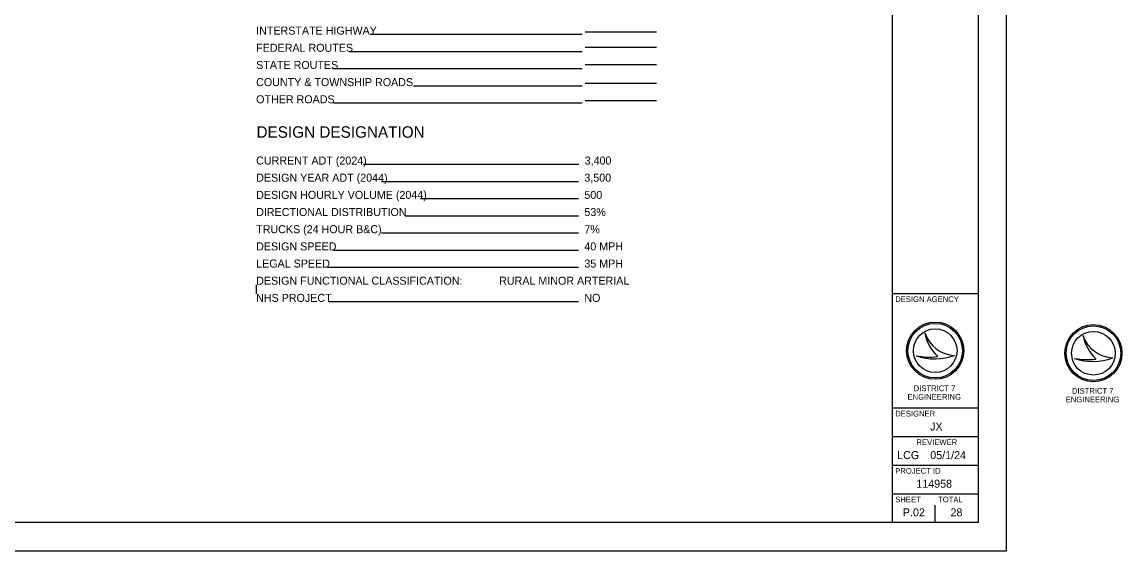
# Model space of a CAD drawing. Extents: x 831 to 1552, y 430 to 870.
# Drawn here: x 1166.7 to 1551.6, y 430 to 614.9 of the extents above; entities that cross this region are included whole.
import ezdxf

# ---------------------------------------------------------------- set-up
doc = ezdxf.new("R2010")
doc.units = 0
for name, color, linetype in [('SC_Scratch1', 7, 'Continuous'), ('SH_Border', 7, 'Continuous'), ('SH_Cut_Line', 7, 'Continuous'), ('SH_Data', 7, 'Continuous'), ('SH_Text', 7, 'Continuous')]:
    doc.layers.add(name, color=color, linetype=linetype)

msp = doc.modelspace()

# ---------------------------------------------------------------- linework, layer by layer
at = {"layer": 'SC_Scratch1'}
for p, q in [((1248.65, 523.06), (1248.65, 519.86)), ((1267.93, 440), (1064.6, 440)), ((1471.27, 440), (1267.93, 440))]:
    msp.add_line(p, q, dxfattribs=at)
at = {"layer": 'SH_Border'}
for p, q in [((1471.27, 440), (1471.27, 860)), ((1471.27, 520), (1501.27, 520)), ((1471.27, 480), (1501.27, 480)), ((1471.27, 470), (1501.27, 470)), ((1471.27, 460), (1501.27, 460)), ((1471.27, 450), (1501.27, 450))]:
    msp.add_line(p, q, dxfattribs=at)
msp.add_lwpolyline([(861.27, 860), (1501.27, 860), (1501.27, 440), (861.27, 440)], close=True, dxfattribs=at)
at = {"layer": 'SH_Cut_Line'}
msp.add_lwpolyline([(831.27, 430), (1511.27, 430), (1511.27, 870), (831.27, 870)], close=True, dxfattribs=at)
at = {"layer": 'SH_Data'}
for p, q in [((1362.77, 610.47), (1288.56, 610.47)), ((1388.77, 611.35), (1363.77, 611.35)), ((1362.77, 604.47), (1281.15, 604.47)), ((1388.77, 605.92), (1363.77, 605.92)), ((1362.77, 598.47), (1275.34, 598.47)), ((1388.77, 599.92), (1363.77, 599.92)), ((1388.77, 593.38), (1363.77, 593.38)), ((1362.77, 592.47), (1303.67, 592.47)), ((1362.77, 586.47), (1275.71, 586.47)), ((1388.77, 587.38), (1363.77, 587.38)), ((1361.61, 565.06), (1286.19, 565.06)), ((1361.5, 559.06), (1292.54, 559.06)), ((1361.5, 553.06), (1306.21, 553.06)), ((1361.5, 547.06), (1300.84, 547.06)), ((1361.5, 541.06), (1292.54, 541.06)), ((1361.5, 535.06), (1275.69, 535.06)), ((1361.5, 529.06), (1273.61, 529.06)), ((1361.5, 517.06), (1274.1, 517.06)), ((1482.62, 506.19), (1482.62, 506.19)), ((1537.98, 505.3), (1537.98, 505.3)), ((1479.61, 498.19), (1479.61, 498.19)), ((1486.27, 500), (1486.27, 500)), ((1493.01, 498.37), (1493.01, 498.37)), ((1534.98, 497.3), (1534.98, 497.3)), ((1548.38, 497.48), (1548.38, 497.48)), ((1478.77, 443.5), (1478.77, 443.5)), ((1486.27, 440), (1486.27, 446))]:
    msp.add_line(p, q, dxfattribs=at)
for centre, radius in [((1486.27, 500), 10), ((1486.27, 500), 9.54), ((1486.27, 500), 9.54), ((1541.63, 499.11), 10), ((1541.63, 499.11), 9.54), ((1541.63, 499.11), 9.54), ((1486.27, 500), 7.64), ((1541.63, 499.11), 7.64)]:
    msp.add_circle(centre, radius, dxfattribs=at)
for centre, radius, start, end in [((1493.59, 509.95), 11.6, 198.9257, 198.9319), ((1498.2, 509.4), 15.91, 191.6379, 191.6421), ((1493.59, 509.95), 11.6, 198.9319, 267.1657), ((1498.2, 509.4), 15.91, 191.6421, 226.0947), ((1548.95, 509.06), 11.6, 198.9257, 198.9319), ((1553.57, 508.51), 15.91, 191.6379, 191.6421), ((1548.95, 509.06), 11.6, 198.9319, 267.1657), ((1553.57, 508.51), 15.91, 191.6421, 226.0947), ((1486.05, 517.4), 20.26, 251.4576, 290.0832), ((1484.23, 523.09), 25.32, 259.4964, 259.4995), ((1486.05, 517.4), 20.26, 251.4527, 251.4576), ((1484.23, 523.09), 25.32, 259.4995, 276.6672), ((1541.42, 516.51), 20.26, 251.4576, 290.0832), ((1539.59, 522.19), 25.32, 259.4964, 259.4995), ((1541.42, 516.51), 20.26, 251.4527, 251.4576), ((1539.59, 522.19), 25.32, 259.4995, 276.6672)]:
    msp.add_arc(centre, radius, start, end, dxfattribs=at)

# ---------------------------------------------------------------- texts
for s, height, p in [('DESIGN DESIGNATION', 4, (1248.77, 574.43)), ('DESIGN AGENCY', 2, (1472.27, 517)), ('DESIGNER', 2, (1472.27, 477)), ('JX', 2.8, (1484.49, 472.1)), ('REVIEWER', 2, (1479.7, 467)), ('LCG', 2.8, (1472.97, 462.1)), ('05/1/24', 2.8, (1484.54, 462.1)), ('PROJECT ID', 2, (1472.27, 457)), ('114958', 2.8, (1479.65, 452.1)), ('SHEET', 2, (1472.27, 447)), ('TOTAL', 2, (1487.27, 447)), ('P.02', 2.8, (1474.96, 442.1)), ('28', 2.8, (1491.62, 442.1))]:
    msp.add_text(s, height=height, dxfattribs=at).set_placement(p)
at = {"layer": 'SH_Text'}
for s, height, p in [('INTERSTATE HIGHWAY', 2.8, (1248.65, 610.47)), ('FEDERAL ROUTES', 2.8, (1248.65, 604.47)), ('STATE ROUTES', 2.8, (1248.65, 598.47)), ('COUNTY & TOWNSHIP ROADS', 2.8, (1248.65, 592.47)), ('OTHER ROADS', 2.8, (1248.65, 586.47)), ('CURRENT ADT (2024)', 2.8, (1248.65, 565.06)), ('3,400', 2.8, (1363.61, 565.06)), ('DESIGN YEAR ADT (2044)', 2.8, (1248.65, 559.06)), ('3,500', 2.8, (1363.5, 559.06)), ('DESIGN HOURLY VOLUME (2044)', 2.8, (1248.65, 553.06)), ('500', 2.8, (1363.5, 553.06)), ('DIRECTIONAL DISTRIBUTION', 2.8, (1248.65, 547.06)), ('53%', 2.8, (1363.5, 547.06)), ('TRUCKS (24 HOUR B&C)', 2.8, (1248.65, 541.06)), ('7%', 2.8, (1363.5, 541.06)), ('DESIGN SPEED', 2.8, (1248.65, 535.06)), ('40 MPH', 2.8, (1363.5, 535.06)), ('LEGAL SPEED', 2.8, (1248.65, 529.06)), ('35 MPH', 2.8, (1363.5, 529.06)), ('DESIGN FUNCTIONAL CLASSIFICATION:', 2.8, (1248.65, 523.06)), ('RURAL MINOR ARTERIAL', 2.8, (1333.68, 523.06)), ('NHS PROJECT', 2.8, (1248.65, 517.06)), ('NO', 2.8, (1363.5, 517.06)), ('DISTRICT 7', 2, (1478.75, 485.85)), ('DISTRICT 7', 2, (1534.11, 484.96)), ('ENGINEERING', 2, (1476.57, 482.85)), ('ENGINEERING', 2, (1531.94, 481.96))]:
    msp.add_text(s, height=height, dxfattribs=at).set_placement(p)

doc.saveas('drawing.dxf')
